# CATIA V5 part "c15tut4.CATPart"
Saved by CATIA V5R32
Part number: Part1
Bounding box of the stored display mesh (mm): x -3 to 154, y -3 to 154, z -47 to 3.015
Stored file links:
  D:\PROJECTS\Project 2022\CATIA V5 6R 2022\Resources\Tutorial Files\c15_catia_v5_6r2022_tut\c15tut4.CATPart
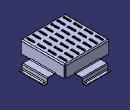
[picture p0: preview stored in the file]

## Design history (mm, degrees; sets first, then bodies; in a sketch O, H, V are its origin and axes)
SheetMetalParameters1: Thickness 1, BendRadius 2, KFactor 0.400515 {= log(min(100,max(20*SheetMetalParameters1.BendRadius,SheetMetalParameters1.Thickness)/SheetMetalParameters1.Thickness))/log(100)/2}, ReliefRadialLength 1, ReliefAxialLength 2, MinimumBendRadius 0
Body1 (main body)
  Sketch1 on xy-plane, origin (0, 0, 0), H (1, 0, 0), V (0, 1, 0)
    line L1 (0, 0) -> (120, 0)
    line L2 (120, 0) -> (120, 120)
    line L3 (120, 120) -> (0, 120)
    line L4 (0, 120) -> (0, 0)
    length L3 = 120
    length L2 = 120
    horizontal: L1 H, L3 H
    vertical: L2 V, L4 V
  Wall1: Thickness 1, Profile Sketch1
  Flange1: Angle 90, Length 34, Radius 2, KFacteur 0.400515 {= log(min(100,max(20*Flange1.Radius,SheetMetalParameters1.Thickness)/SheetMetalParameters1.Thickness))/log(100)/2}, Guide edge [face of Wall1 | face of Wall1]
  Flange2: Angle 90, Length 34, Radius 2, KFacteur 0.400515 {= log(min(100,max(20*Flange2.Radius,SheetMetalParameters1.Thickness)/SheetMetalParameters1.Thickness))/log(100)/2}, Guide edge [face of Wall1 | face of Wall1]
  Flange3: Angle 90, Length 34, Radius 2, KFacteur 0.400515 {= log(min(100,max(20*Flange3.Radius,SheetMetalParameters1.Thickness)/SheetMetalParameters1.Thickness))/log(100)/2}, Guide edge [face of Wall1 | face of Wall1]
  Flange4: Angle 90, Length 34, Radius 2, KFacteur 0.400515 {= log(min(100,max(20*Flange4.Radius,SheetMetalParameters1.Thickness)/SheetMetalParameters1.Thickness))/log(100)/2}, Guide edge [face of Wall1 | face of Wall1]
  d_NewWallOnEdge1: NewWallOnEdge_Edge edge [face of Flange3 | face of Flange3], NewWallOnEdge_Length 21, NewWallOnEdge_HeightLimitOffset 0, NewWallOnEdge_WidthOffset1 -25, NewWallOnEdge_WidthOffset2 -25, NewWallOnEdge_Angle 90, NewWallOnEdge_BendRadiusValue 2 {= SheetMetalParameters1.BendRadius}, NewWallOnEdge_BendTable SheetMetalParameters1, KFacteur 0.400515 {= log(min(100,max(20*d_NewWallOnEdge1.Radius,SheetMetalParameters1.Thickness)/SheetMetalParameters1.Thickness))/log(100)/2}
  Flange5: Angle 90, Length 13, Radius 1, KFacteur 0.325257 {= log(min(100,max(20*Flange5.Radius,SheetMetalParameters1.Thickness)/SheetMetalParameters1.Thickness))/log(100)/2}, Guide edge [face of d_NewWallOnEdge1 | face of d_NewWallOnEdge1]
  d_NewWallOnEdge2: NewWallOnEdge_Edge edge [face of Flange5 | face of Flange5], NewWallOnEdge_Length 10, NewWallOnEdge_HeightLimitOffset 0, NewWallOnEdge_WidthOffset1 0, NewWallOnEdge_WidthOffset2 0, NewWallOnEdge_Angle 90, NewWallOnEdge_BendRadiusValue 2 {= SheetMetalParameters1.BendRadius}, NewWallOnEdge_BendTable SheetMetalParameters1, KFacteur 0.400515 {= log(min(100,max(20*d_NewWallOnEdge2.Radius,SheetMetalParameters1.Thickness)/SheetMetalParameters1.Thickness))/log(100)/2}
  d_NewWallOnEdge3: NewWallOnEdge_Edge edge [face of Flange2 | face of Flange2], NewWallOnEdge_Length 21, NewWallOnEdge_HeightLimitOffset 0, NewWallOnEdge_WidthOffset1 -25, NewWallOnEdge_WidthOffset2 -25, NewWallOnEdge_Angle 90, NewWallOnEdge_BendRadiusValue 2 {= SheetMetalParameters1.BendRadius}, NewWallOnEdge_BendTable SheetMetalParameters1, KFacteur 0.400515 {= log(min(100,max(20*d_NewWallOnEdge3.Radius,SheetMetalParameters1.Thickness)/SheetMetalParameters1.Thickness))/log(100)/2}
  Flange6: Angle 90, Length 13, Radius 1, KFacteur 0.325257 {= log(min(100,max(20*Flange6.Radius,SheetMetalParameters1.Thickness)/SheetMetalParameters1.Thickness))/log(100)/2}, Guide edge [face of d_NewWallOnEdge3 | face of d_NewWallOnEdge3]
  d_NewWallOnEdge4: NewWallOnEdge_Edge edge [face of Flange6 | face of Flange6], NewWallOnEdge_Length 10, NewWallOnEdge_HeightLimitOffset 0, NewWallOnEdge_WidthOffset1 0, NewWallOnEdge_WidthOffset2 0, NewWallOnEdge_Angle 90, NewWallOnEdge_BendRadiusValue 2 {= SheetMetalParameters1.BendRadius}, NewWallOnEdge_BendTable SheetMetalParameters1, KFacteur 0.400515 {= log(min(100,max(20*d_NewWallOnEdge4.Radius,SheetMetalParameters1.Thickness)/SheetMetalParameters1.Thickness))/log(100)/2}
  Sketch2 on face of d_NewWallOnEdge2, origin (31.3691, 147.6369, -46), H (1, 0, 0), V (0, 1, 0)
    point P1 (-1.3691, 2.3631)
    reference projected line E1 (-6.3691, 6.3631) -> (63.6309, 6.3631) from edge [face of d_NewWallOnEdge2 | face of d_NewWallOnEdge2]
    reference projected line E2 (-6.3691, -0.6369) -> (-6.3691, 6.3631) from edge [face of d_NewWallOnEdge2 | face of d_NewWallOnEdge2]
    distance P1 E1 = 4
    distance P1 E2 = 5
  Hole1: placed by Sketch2, at (30, 150, -46) direction (0, 0, -1), diameter 3, through (limit type 6)
  Sketch3 on face of d_NewWallOnEdge2, origin (79.2942, 150.7856, -46), H (1, 0, 0), V (0, 1, 0)
    point P1 (10.7058, -0.7856)
    reference projected line E1 (-54.2942, 3.2144) -> (15.7058, 3.2144) from edge [face of d_NewWallOnEdge2 | face of d_NewWallOnEdge2]
    reference projected line E2 (15.7058, 3.2144) -> (15.7058, -3.7856) from edge [face of d_NewWallOnEdge2 | face of d_NewWallOnEdge2]
    distance P1 E1 = 4
    distance P1 E2 = 5
  Hole2: placed by Sketch3, at (90, 150, -46) direction (0, 0, -1), diameter 3, through (limit type 6)
  Sketch4 on face of d_NewWallOnEdge4, origin (148.0642, 84.3582, -46), H (1, 0, 0), V (0, 1, 0)
    point P1 (1.9358, 5.6418)
    reference projected line E1 (5.9358, 10.6418) -> (5.9358, -59.3582) from edge [face of d_NewWallOnEdge4 | face of d_NewWallOnEdge4]
    reference projected line E2 (-1.0642, 10.6418) -> (5.9358, 10.6418) from edge [face of d_NewWallOnEdge4 | face of d_NewWallOnEdge4]
    distance P1 E1 = 4
    distance P1 E2 = 5
  Hole3: placed by Sketch4, at (150, 90, -46) direction (0, 0, -1), diameter 3, through (limit type 6)
  Sketch5 on face of d_NewWallOnEdge4, origin (149.1042, 61.7681, -46), H (1, 0, 0), V (0, 1, 0)
    point P1 (0.8958, -31.7681)
    reference projected line E1 (4.8958, -36.7681) -> (-2.1042, -36.7681) from edge [face of d_NewWallOnEdge4 | face of d_NewWallOnEdge4]
    reference projected line E2 (4.8958, 33.2319) -> (4.8958, -36.7681) from edge [face of d_NewWallOnEdge4 | face of d_NewWallOnEdge4]
    distance E1 P1 = 5
    distance P1 E2 = 4
  Hole4: placed by Sketch5, at (150, 30, -46) direction (0, 0, -1), diameter 3, through (limit type 6)
  Sketch6 on face of Wall1, origin (0, 0, 0), H (1, 0, 0), V (0, -1, 0)
    line L1 (112, -115) -> (109.5, -115)
    line L2 (109.5, -115) -> (109.5, -95)
    line L3 (109.5, -95) -> (112, -95)
    line L4 (112, -95) -> (112, -115)
    reference projected line E1 (0, -123) -> (120, -123) from edge [face of Flange3 | face of Flange3]
    reference projected line E2 (123, -120) -> (123, 0) from edge [face of Flange2 | face of Flange2]
    distance L2 L4 = 2.5
    length L2 = 20
    distance L1 E1 = 8
    distance L4 E2 = 11
    horizontal: L1 H, L3 H
    vertical: L2 V, L4 V
  d_Stamp1: NewRoot_AttribNormalisation "No Standard", Stamp_FilletRadius 0.25
  RectPattern1: of d_Stamp1, direction 1 instances 7, spacing 17, along edge [face of Flange3 | face of Flange3] reversed, direction 2 instances 4, spacing 30, along edge [face of Flange2 | face of Flange2]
